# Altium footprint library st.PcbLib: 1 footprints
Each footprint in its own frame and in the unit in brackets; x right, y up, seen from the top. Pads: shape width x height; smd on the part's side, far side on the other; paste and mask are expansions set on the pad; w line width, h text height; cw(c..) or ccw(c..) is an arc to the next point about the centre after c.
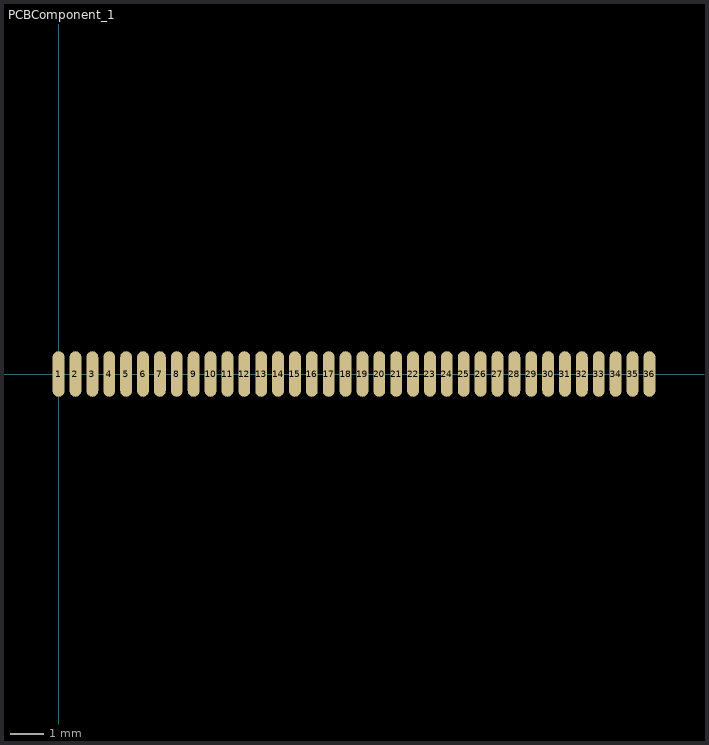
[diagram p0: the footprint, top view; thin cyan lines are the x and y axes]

## PCBComponent_1 [mm]
pads (36):
  oval 0.35x1.35 all layers, no hole: 1(0,0) 2(0.5,0) 3(1,0) 4(1.5,0) 5(2,0) 6(2.5,0) 7(3,0) 8(3.5,0) 9(4,0) 10(4.5,0) 11(5,0) 12(5.5,0) 13(6,0) 14(6.5,0) 15(7,0) 16(7.5,0) 17(8,0) 18(8.5,0) 19(9,0) 20(9.5,0) 21(10,0) 22(10.5,0) 23(11,0) 24(11.5,0) 25(12,0) 26(12.5,0) 27(13,0) 28(13.5,0) 29(14,0) 30(14.5,0) 31(15,0) 32(15.5,0) 33(16,0) 34(16.5,0) 35(17,0) 36(17.5,0)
